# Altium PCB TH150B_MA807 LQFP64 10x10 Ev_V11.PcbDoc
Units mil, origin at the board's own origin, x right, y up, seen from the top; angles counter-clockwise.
Board outline 2850 x 2505 mil, 2 copper layers (Top Layer, Bottom Layer); 50 components, 79 nets, 342 pads, 184 vias.
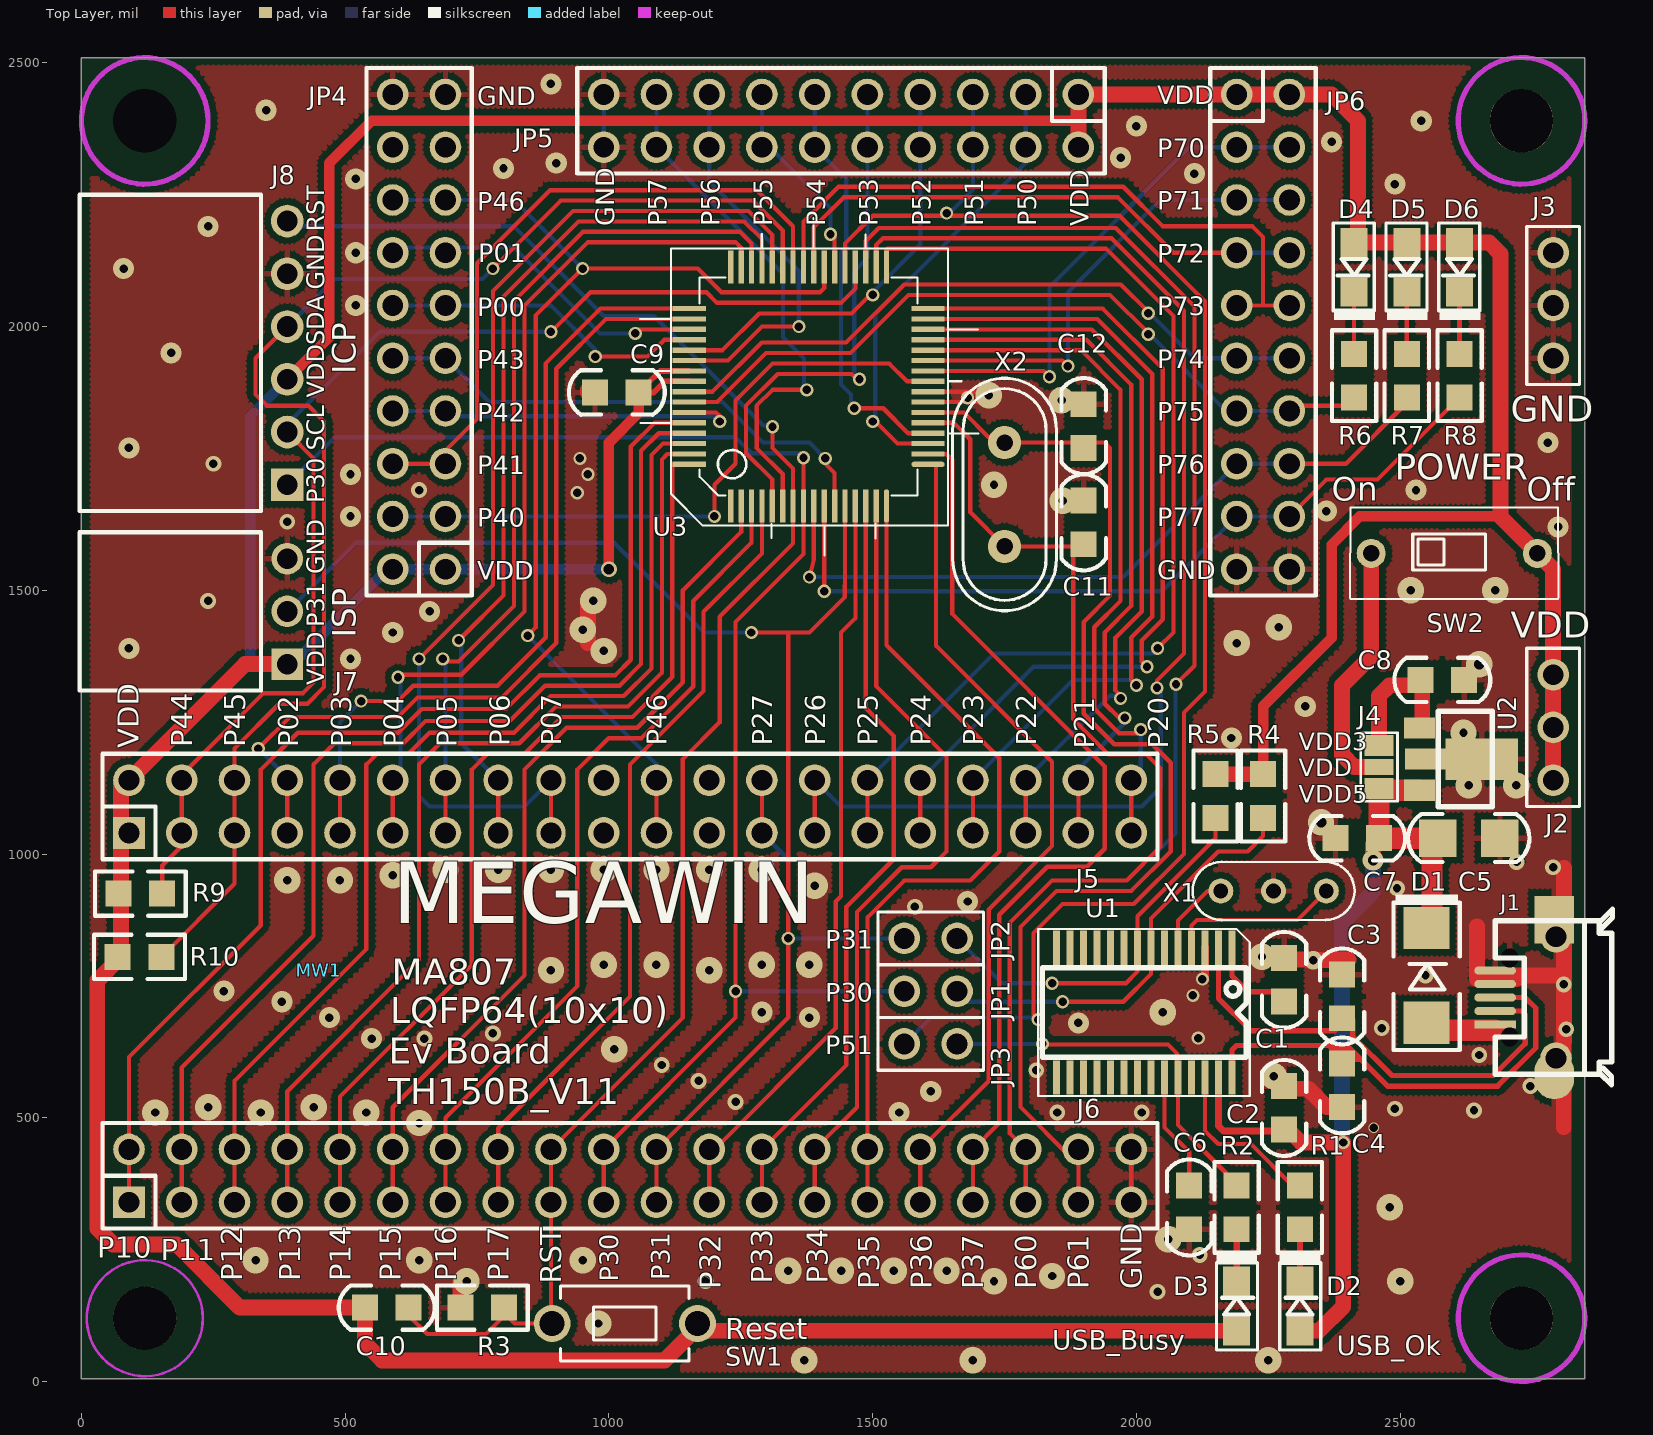
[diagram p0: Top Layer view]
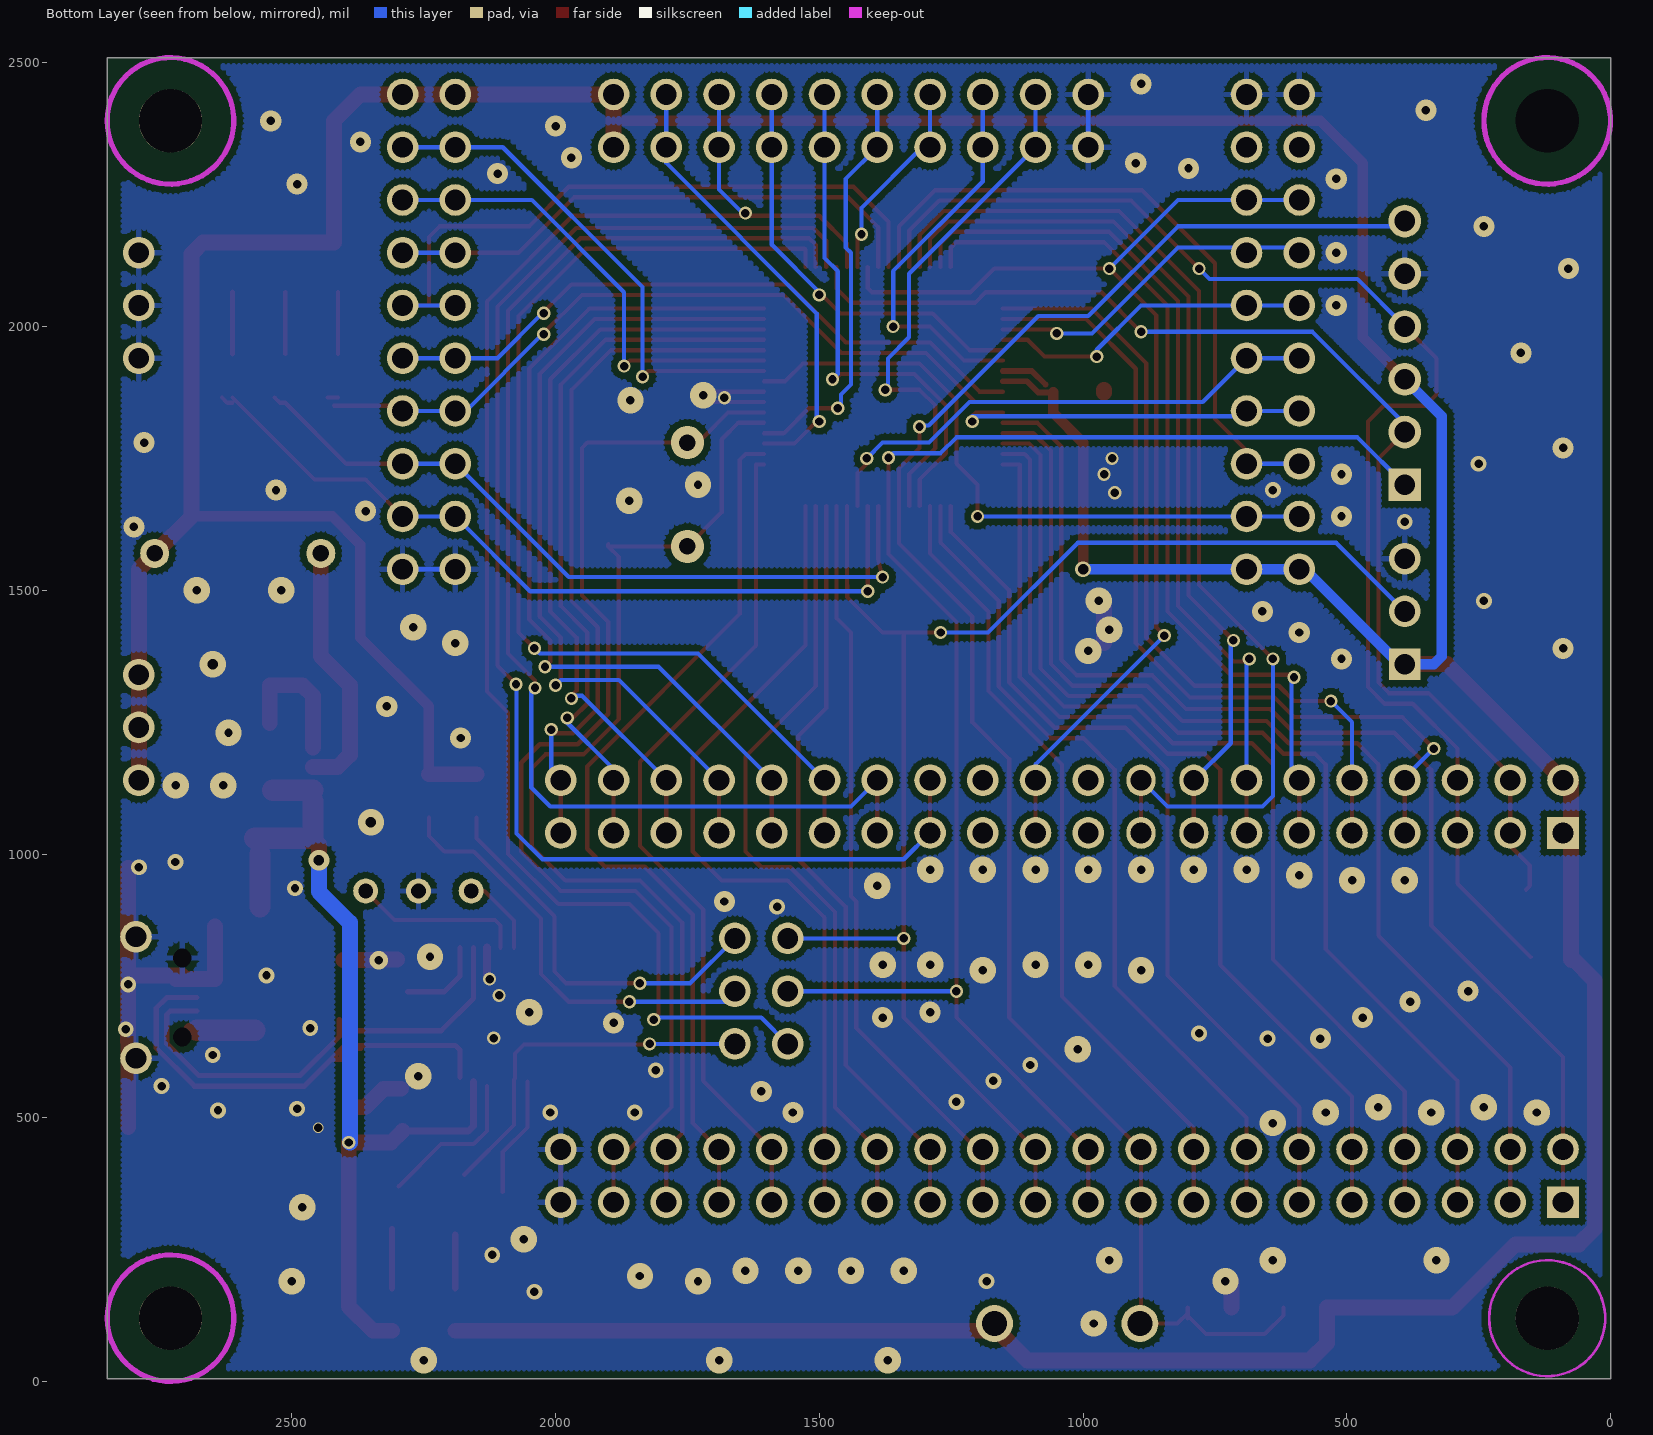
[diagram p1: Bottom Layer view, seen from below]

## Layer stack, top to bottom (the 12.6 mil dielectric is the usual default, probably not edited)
Top Layer: signal copper 1.4
Dielectric: dielectric 12.6, FR-4, Dk 4.8
Bottom Layer: signal copper 1.4

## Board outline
0,5 0,2510 2850,2510 2850,5

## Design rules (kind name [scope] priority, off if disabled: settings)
Clearance 12 [All] p1 off: gap=12
Clearance 10 [All] p2 off: gap=10
Clearance 6 [All] p3: gap=6
ComponentClearance [All] p1 off: gap=10 collisioncheckmode=3 verticalgap=10 showdistances=FALSE
HoleSize [All] p1: absolutevalues=TRUE maxlimit=500 minlimit=1 maxpercent=80.000 minpercent=20.000
MinimumSolderMaskSliver [All] p1 off: minsoldermaskwidth=10
PolygonConnect VIA [ISVIA] p1: connectstyle=Direct reliefconductorwidth=10 reliefentries=4 polygonreliefangle="90 Angle"
PolygonConnect [All] p2: connectstyle=Relief reliefconductorwidth=10 reliefentries=4 polygonreliefangle="90 Angle"
RoomDefinition "TH150B_MA807 LQFP64 Ev_V10" [InComponentClass('TH150B_MA807 LQFP64 Ev_V10')] p1: confinementstyle=ConfineIn formatcopy=TRUE lockcomponents=FALSE outline -530,-1140 3370,-1140 3370,2770 -530,2770
RoutingVias [All] p1: holewidth=16 width=25 viastyle="Through Hole" minholewidth=16 minwidth=24 maxholewidth=28 maxwidth=50
SilkToSilkClearance [All] p1 off: silktosilkclearance=10
SilkscreenOverComponentPads [All] p1 off: minsilkscreentomaskgap=10
SolderMaskExpansion [All] p1 off: expansion=4
Width [All] p1: maxlimit=200 minlimit=6 preferedwidth=10
23 further rules are at their usual default settings.

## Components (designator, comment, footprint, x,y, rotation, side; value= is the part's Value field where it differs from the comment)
C1 "4.7uF" 0805C 2280,761.34 r90 top
C2 "0.1uF" 0805C 2280,518.66 r270 top
C3 "15pF" 0805C 2390,730 r90 top
C4 "15pF" 0805C 2390,561.34 r270 top
C5 "4.7uF" 1206C 2630,1030 r0 top
C6 "0.1uF" 0805C 2100,330 r90 top
C7 "0.1uF" 0805C 2418.66,1030 r180 top
C8 "4.7uF" 0805C 2580,1330 r0 top
C9 "0.1uF" 0805C 1014.92,1875.08 r180 top
C10 "1u" 0805C 578.66,140 r0 top
C11 "NC" 0805C 1900,1628.66 r90 top
C12 "NC" 0805C 1900,1811.34 r90 top
D1 "1N5817" D5817_SMD_1 2550,770 r270 top
D2 "Yellow" 0805D 2310,143.08 r90 top
D3 "RED" 0805D 2190,143.08 r90 top
D4 "Green" 0805D 2412.54,2112.47 r270 top
D5 "Red" 0805D 2512.54,2112.47 r270 top
D6 "Green" 0805D 2612.54,2112.47 r270 top
J1 "Micro USB母座" JACK_USB_SMD290X220P065 2680,727.95 r180 top
J2 "*" PS3P254 2790,1140 r90 top
J3 "*" PS3P254 2790,2140 r270 top
J4 "*" JUMP3_SMD 2460,1165 r90 top
J5 "*" PS20X2P254#1 90,1040 r0 top locked
J6 "*" PS20X2P254#2 90,340 r0 top locked
J7 "*" PS3P254f_90 390,1360 r90 top
J8 "*" PS6P254F_90 390,1700 r90 top
JP1 "JUMPER2" PS2P254 1560,740 r0 top
JP2 "JUMPER2" PS2P254 1560,840 r0 top
JP3 "JUMPER2" PS2P254 1560,640 r0 top
JP4 "*" PS10X2P254 690,1540 r90 top
JP5 "*" PS10X2P254 1890,2440 r180 top
JP6 "*" PS10X2P254 2190,2440 r270 top
MW1 "MW-A4" MEGAWIN_T 450,780 r0 top
R1 "1K" 0805R 2310,330 r270 top
R2 "1K" 0805R 2190,330 r270 top
R3 "47K" 0805R 760,140 r0 top
R4 "4.7K" 0805R 2240,1110 r270 top
R5 "4.7K" 0805R 2150,1110 r270 top
R6 "1K" 0805R 2412.54,1906.89 r90 top
R7 "1K" 0805R 2512.54,1906.89 r90 top
R8 "1K" 0805R 2612.54,1906.89 r90 top
R9 "4.7K" 0805R 111.66,925 r180 top
R10 "4.7K" 0805R 110,805 r180 top
SW1 "SW TACT-SPST" SW_T_2P 1030,110 r180 top
SW2 "-" DIP2_SW 2445.04,1570 r0 top
U1 "MA101_TSSOP28" TSSOP28_170P065 2014.84,699.52 r180 top
U2 "AIC1734-33(SOT-89)" SOT89 2536.53,1180 r270 top
U3 "MA807_LQFP64(10x10)" QFP64_10X10P050 1230.95,1660 r90 top locked (schematic designator U1)
X1 "6MHz" X3P 2360,930 r180 top
X2 "NC" X49U 1750,1681.58 r90 top

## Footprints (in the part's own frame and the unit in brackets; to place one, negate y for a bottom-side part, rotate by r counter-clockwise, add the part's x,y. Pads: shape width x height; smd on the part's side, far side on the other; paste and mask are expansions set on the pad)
0805C [mm]
  rect 1.25x1.25 smd: 1(-1.05,0) 2(1.05,0)
  silkscreen extent -2.31,-1.07 2.31,1.07
0805D [mm]
  rect 1.4x1.3 smd: 1(-1.192,0) 2(1.192,0)
  silkscreen extent -2.12,-1 2.53,0.98
0805R [mm]
  rect 1.25x1.25 smd: 1(-1.05,0) 2(1.05,0)
  silkscreen extent -2.18,-1.07 2.18,1.07
1206C [mm]
  rect 1.8x1.8 smd: 1(-1.5,0) 2(1.5,0)
  silkscreen extent -2.92,-1.15 2.92,1.16
D5817_SMD_1 [mil]
  rect 80x86.61 smd: 1(90,0) 2(-90,0)
  silkscreen extent -153,-63 142,63
DIP2_SW [mm]
  round 1.4 hole 0.8: 1(0,0) 2(8,0)
  silkscreen extent -1.02,-2.2 9.02,2.2
JACK_USB_SMD290X220P065 [mm]
  rect 1.9x1.8 on Mech2: 0(-2.85,-1.15) 0(-2.85,1.15)
  round 0.8 hole 0.9 unplated: 1(-0.7,1.9) 5(-0.7,-1.9)
  rect 2x0.4 smd: 1(0,1.3)
  oval 2x0.4 smd: 2(0,0.65) 3(0,0) 4(0,-0.65) 5(0,-1.3)
  round 1.524 hole 1: 5(-2.931,2.921) 5(-2.931,-2.921)
  oval 1.9x2.3 smd: 5(-2.85,3.75)
  rect 1.9x2.3 smd: 5(-2.85,-3.75)
  silkscreen extent -5.65,-4.25 -0.01,4.2
JUMP3_SMD [mil]
  rect 40x55 smd: 1(-41,0) 3(41,0)
  rect 30x55 smd: 2(0,0)
  silkscreen extent -65,-35 65,35
MEGAWIN_T [mil]
PS2P254 [mil]
  round 60 hole 39.37: 1(0,0) 2(100,0)
  silkscreen extent -50,-50 150,50
PS3P254 [mil]
  round 60 hole 39.37: 1(0,0) 2(100,0) 3(200,0)
  silkscreen extent -50,-50 250,50
PS3P254f_90 [mil]
  rect 60x60 hole 39.37: 1(0,0)
  round 60 hole 39.37: 2(100,0) 3(200,0)
  silkscreen extent -50,50 250,394
PS6P254F_90 [mil]
  rect 62x62 hole 39.37: 1(0,0)
  round 62 hole 39.37: 2(100,0) 3(200,0) 4(300,0) 5(400,0) 6(500,0)
  silkscreen extent -50,50 550,394
PS10X2P254 [mil]
  round 60 hole 39.37: 1(0,0) 2(0,100) 3(100,0) 4(100,100) 5(200,0) 6(200,100) 7(300,0) 8(300,100) 9(400,0) 10(400,100) 11(500,0) 12(500,100) 13(600,0) 14(600,100) 15(700,0) 16(700,100) 17(800,0) 18(800,100) 19(900,0) 20(900,100)
  silkscreen extent -50,-50 950,150
PS20X2P254#1 [mil]
  rect 60x60 hole 39.37: 1(0,0)
  round 60 hole 39.37: 2(0,100) 3(100,0) 4(100,100) 5(200,0) 6(200,100) 7(300,0) 8(300,100) 9(400,0) 10(400,100) 11(500,0) 12(500,100) 13(600,0) 14(600,100) 19(900,0) 20(900,100) 21(1000,0) 22(1000,100) 23(1100,0) 24(1100,100) 25(1200,0) 26(1200,100) 27(1300,0) 28(1300,100) 29(1400,0) 30(1400,100) 31(1500,0) 32(1500,100) 33(1600,0) 34(1600,100) 35(1700,0) 36(1700,100) 37(1800,0) 38(1800,100) 39(1900,0) 40(1900,100)
  oval 55x60 hole 39.37: 15(700,0) 16(700,100) 17(800,0) 18(800,100)
  silkscreen extent -50,-50 1950,150
PS20X2P254#2 [mil]
  rect 60x60 hole 39.37: 1(0,0)
  round 60 hole 39.37: 2(0,100) 3(100,0) 4(100,100) 5(200,0) 6(200,100) 7(300,0) 8(300,100) 9(400,0) 10(400,100) 11(500,0) 12(500,100) 13(600,0) 14(600,100) 15(700,0) 16(700,100) 17(800,0) 18(800,100) 19(900,0) 20(900,100) 21(1000,0) 22(1000,100) 23(1100,0) 24(1100,100) 25(1200,0) 26(1200,100) 27(1300,0) 28(1300,100) 29(1400,0) 30(1400,100) 31(1500,0) 32(1500,100) 33(1600,0) 34(1600,100) 35(1700,0) 36(1700,100) 37(1800,0) 38(1800,100) 39(1900,0) 40(1900,100)
  silkscreen extent -50,-50 1950,150
QFP64_10X10P050 [mm]
  rect 1.6x0.254 smd: 1(0,0) 2(0,-0.5) 3(0,-1) 4(0,-1.5) 5(0,-2) 6(0,-2.5) 7(0,-3) 8(0,-3.5) 9(0,-4) 10(0,-4.5) 11(0,-5) 12(0,-5.5) 13(0,-6) 14(0,-6.5) 15(0,-7) 33(11.5,-7.5) 34(11.5,-7) 35(11.5,-6.5) 36(11.5,-6) 37(11.5,-5.5) 38(11.5,-5) 39(11.5,-4.5) 40(11.5,-4) 41(11.5,-3.5) 42(11.5,-3) 43(11.5,-2.5) 44(11.5,-2) 45(11.5,-1.5) 46(11.5,-1) 47(11.5,-0.5) 48(11.5,0)
  oval 1.6x0.254 smd: 16(0,-7.5)
  oval 0.254x1.6 smd: 17(2,-9.5)
  rect 0.254x1.6 smd: 18(2.5,-9.5) 19(3,-9.5) 20(3.5,-9.5) 21(4,-9.5) 22(4.5,-9.5) 23(5,-9.5) 24(5.5,-9.5) 25(6,-9.5) 26(6.5,-9.5) 27(7,-9.5) 28(7.5,-9.5) 29(8,-9.5) 30(8.5,-9.5) 31(9,-9.5) 32(9.5,-9.5) 49(9.5,2) 50(9,2) 51(8.5,2) 52(8,2) 53(7.5,2) 54(7,2) 55(6.5,2) 56(6,2) 57(5.5,2) 58(5,2) 59(4.5,2) 60(4,2) 61(3.5,2) 62(3,2) 63(2.5,2) 64(2,2)
  silkscreen extent -2.4,-11.92 13.86,4.36
SOT89 [mm]
  rect 1.016x1.5 smd: 1(-1.5,0) 3(1.5,0)
  rect 2x3.5 smd: 2(0,3)
  rect 1.016x2.6 smd: 2(0,0.6)
  silkscreen extent -2.3,0.9 2.3,3.5
SW_T_2P [mil]
  round 70 hole 47.24: 1(-137.79,0) 2(137.79,0)
  silkscreen extent -122,-71 122,71
TSSOP28_170P065 [mil]
  rect 13x65 smd: 1(-166.34,-123) 2(-140.75,-123) 3(-115.16,-123) 4(-89.57,-123) 5(-63.98,-123) 6(-38.39,-123) 7(-12.79,-123) 8(12.8,-123) 9(38.39,-123) 10(63.98,-123) 11(89.57,-123) 12(115.16,-123) 13(140.75,-123) 14(166.34,-123) 15(166.34,123) 16(140.75,123) 17(115.16,123) 18(89.57,123) 19(63.98,123) 20(38.39,123) 21(12.8,123) 22(-12.79,123) 23(-38.39,123) 24(-63.98,123) 25(-89.57,123) 26(-115.16,123) 27(-140.75,123) 28(-166.34,123)
  silkscreen extent -200,-158 201,158
X3P [mm]
  round 1.2 hole 0.711: 1(0,0) 2(5.08,0) 3(2.54,0)
  silkscreen extent -1.36,-1.4 6.44,1.4
X49U [mm]
  round 1.6 hole 0.8: 1(-2.5,0) 2(2.5,0)
  silkscreen extent -5.6,-2.5 5.6,2.5

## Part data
C1 C5 C8: library part CAP
C2 C3 C4 C6 C7 C9: library part "CAP NP"
C10: library part C
C11 C12: library part "C NP"
D1: library part DIODE_ZD, "Schottky Diode"
D2 D3 D4 D5 D6: library part LED
J1: library part CON5, "Connector"
J2 J3 J4 J7: library part CON3
J5 J6: library part CON40A
J8: library part CON6
JP4 JP5 JP6: library part CON10X2
R1 R2 R4 R5 R6 R7 R8: library part R_Dup1
R3 R9 R10: library part R
SW2: library part SW-2
U2: library part AIC1734-33(SOT-89)_0
U3: library part MG82Fx3xx_0
X1: library part CRYSTAL_RC
X2: library part CRYSTAL

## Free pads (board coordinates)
  round 120 hole 120 unplated: 0(120,120) 0(2730,120) 0(2730,2390)
  round 40 hole 120 unplated: 0(120,2390)

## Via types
v1: diameter 50, hole 16, Top Layer to Bottom Layer, tented both sides, 58 vias
v2: diameter 25, hole 16, Top Layer to Bottom Layer, tented both sides, 54 vias
v3: diameter 40, hole 16, Top Layer to Bottom Layer, tented both sides, 39 vias
v4: diameter 30, hole 16, Top Layer to Bottom Layer, tented both sides, 27 vias
v5: diameter 50, hole 20, Top Layer to Bottom Layer, tented both sides, 2 vias
v6: diameter 30, hole 20, Top Layer to Bottom Layer, tented both sides, 1 vias
v7: diameter 39.37, hole 20, Top Layer to Bottom Layer, tented both sides, 1 vias
v8: diameter 20, hole 16, Top Layer to Bottom Layer, tented both sides, 1 vias
v9: diameter 35, hole 16, Top Layer to Bottom Layer, tented both sides, 1 vias

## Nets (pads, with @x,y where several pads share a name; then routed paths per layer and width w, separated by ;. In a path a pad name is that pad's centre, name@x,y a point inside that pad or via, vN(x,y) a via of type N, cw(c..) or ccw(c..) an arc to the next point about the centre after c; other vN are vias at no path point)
D+: C4.1 J1.3 U1.28 | length 938.6
  Top Layer w10: U1.28 2181.18,628.18 2190,637 2386.34,637 ; 2368.82,631.18 2390,631.18 2392.16,631.18 ; C4.1@2390,611.18 2424.48,611.18 ; C4.1@2405.33,618.01 2392.16,631.18 ; J1.3 2736.93,727.95 2757,707.88 2757,632.23 2684.77,560 2476,560 2411.66,624.34 2399,637 2386.34,637 ; 2386.34,637 2392.16,631.18
D-: C3.1 J1.2 U1.2 | length 907.4
  Top Layer w10: U1.2 2155.59,726.25 2216.84,665 2376,665 2390,679 C3.1@2406,679 ; C3.1@2410,686 2410,654.28 2484.28,580 2676.49,580 2737,640.51 2737,695.8 2730.43,702.36 J1.2
GND_POWER: C1.2 C2.1 C3.2 C4.2 C5.2 C6.1 C7.2 C8.2 C9.2 C11.2 C12.2 J1.4 J1.5 J3.1 J3.2 J3.3 J6.39 J6.40 J7.3 J8.5 JP4.19 JP4.20 JP5.19 JP5.20 JP6.19 JP6.20 R3.1 U1.3 U2.2 U3.23 U3.24 X1.3 | length 1666.9
  Top Layer w8: U3.23 1680,1856.85 v1@1705.98,1856.85 ; U3.24 1680,1876.53 v1@1705.98,1876.53 ; J6.39 J6.40
  Top Layer w15: v2@2130,763 U1.3
  Top Layer w30: R3.1 v1@718.66,190 ; 960,1400 960,1425 v1@960,1480 ; C9.2@960,1875.08 C9.2@960,1880 ; C2.1@2293,555 2326,555 2361,520 C4.2 ; C1.2@2300,800 v9@2327.66,800 ; v9@2330,799 v9(2335,799) 2390,799 2402,799 ; 2645.87,763 2680,763 2719.29,763 ; 2645.87,765.59 2645.87,779.13 2645.87,862.68 ; 2708.54,770 2805.63,770 ; 2810,482 2810.17,580.28 2810.23,612.93 2810.33,667.96 2810.48,752.95 2810.64,842.93 2810.69,875.56 2810.87,973.68
  Bottom Layer w8: JP5.20 JP5.19 ; JP6.19 JP6.20
  other v1: 1370,40 1690,40 2250,40 980,110 730,190 1730,190 2500,190 1840,200 1340,210 1440,210 1540,210 1640,210 330,230 640,230 950,230 2060,270 2480,330 640,490 140,510 340,510 540,510 240,520 440,520 2260,579 1010,630 2050,700 890,780 1190,780 990,790 1090,790 1290,790 1380,790 2238,805 1390,940 390,950 490,950 590,960 690,970 790,970 890,970 990,970 1090,970 1190,970 1290,970 2630,1130 2720,1130 2620,1230 990,1385 2190,1400 950,1425 2270,1430 970,1480 2520,1500 2680,1500 1860,1670 1730,1700 1858,1860 1720,1870
  other v2: 2117,651 2107,732 2125,763 940,1685 960,1720 945,1750 1680,1865
  other v3: 1550,510 1610,550 550,650 1890,680 470,690 1380,690 1290,700 380,720 270,740 1680,910 2180,1220 2320,1280 510,1370 90,1390 590,1420 660,1460 2799.51,1620.07 510,1640 2360,1650 2530,1690 510,1720 90,1770 2780,1780 170,1950 520,2040 80,2110 520,2140 240,2190 2490,2270 520,2280 2110,2290 800,2300 900,2310 1970,2320 2370,2350 2000,2380 2540,2390 350,2410 890,2460
  other v4: 2040,170 1182.79,190 2120,240 1850,510 2010,510 2640,514 2490,517 1240,530 2747,560 1170,570 1810,590 1100,600 2650,619 650,650 780,660 2815,667.95 2465,670 2810,752.95 2548,770 1580,900 2494,935 2790,975 2720.73,984.9 240,1480 390,1630 640,1690 250,1740
  other v5: 2350,1060 2650,1360
  other v8: 2450,481
MA101_RX: JP2.2 R5.2 U1.8 | length 739.3
  Top Layer w8: v2(1840,755) 1980,755 2002.05,777.05 U1.8 2002.05,882.05 2150,1030 R5.2
  Bottom Layer w8: JP2.2 1745,755 v2(1840,755)
MA101_TX: JP1.2 R4.2 U1.7 | length 806.2
  Top Layer w8: v2(1860,720) 1975,720 2027.64,772.64 U1.7 2027.64,877.64 2155,1005 2211,1005 2240,1034 R4.2
  Bottom Layer w8: JP1.2@1660,720 v2(1860,720)
NetC1_1: C1.1 U1.1 | length 165
  Top Layer w10: U1.1 2181.18,768.82 2211.34,738.66 C1.1@2280,738.66
NetC6_2: C6.2 U1.23 | length 229.4
  Top Layer w8: U1.23@2053.23,569 2053.23,481.77 2100,435 C6.2 C6.2@2100,359
NetD1_1: D1.1 J1.1 | length 120.9
  Top Layer w30: 2680,665.87 2690.87,665.87
  Top Layer w40: D1.1@2570,665.87 2680,665.87
NetD2_2: D2.2 R1.2 | length 111.7
  Top Layer w12: D2.2@2310,176.92 D2.2 R1.2
NetD3_2: D3.2 R2.2 | length 101.7
  Top Layer w12: D3.2@2190,176.92 D3.2 R2.2@2190,278.66
NetD4_2: D4.2 R6.2 | length 117.3
  Top Layer w8: R6.2 D4.2
NetD5_2: D5.2 R7.2 | length 117.3
  Top Layer w8: R7.2 D5.2
NetD6_2: D6.2 R8.2 | length 117.3
  Top Layer w10: R8.2 D6.2
NetJ4_2: J4.2 SW2.1 | length 484.3
  Top Layer w30: SW2.1 2445.04,1375.04 2390,1320 2390,1187.99 2412.99,1165 J4.2
NetU1_4: U1.4 X1.1 | length 324.6
  Top Layer w8: U1.4 2104.41,864.41 2115,875 2305,875 X1.1
NetU1_5: U1.5 X1.2 | length 155.8
  Top Layer w8: U1.5 2078.82,873.82 2135,930 X1.2
P00: JP4.11 JP4.12 U3.52 | length 620.2
  Top Layer w8: v2(974,1943) 1073,1943 1104.96,1974.96 U3.52
  Bottom Layer w8: JP4.12 JP4.11 890,2040 974,1956 v2@974,1946
P01: JP4.13 JP4.14 U3.51 | length 619.7
  Top Layer w8: v2@1050,1994.65 U3.51
  Bottom Layer w8: JP4.14@600,2150 690,2150 820,2150 983,1987 v2(1050,1987)
P02: J5.7 J5.8 U3.50 | length 1641.9
  Top Layer w8: v2(335,1200) 395,1260 600,1260 637,1297 797,1297 900,1400 900,1920 994.33,2014.33 U3.50 ; J5.7 J5.8
  Bottom Layer w8: v2(335,1200) 390,1145 J5.8
P03: J5.9 J5.10 U3.49 | length 1501.6
  Top Layer w8: J5.9 J5.10 ; v2(530,1290) 600,1290 629,1319 789,1319 880,1410 880,1930 984.02,2034.02 U3.49
  Bottom Layer w8: J5.10 490,1250 v2(530,1290)
P04: J5.11 J5.12 U3.47 | length 1653.1
  Top Layer w8: J5.11 J5.12 ; v2(600,1335) 605,1340 720,1340 840,1460 840,2040 960,2160 1240,2160 1250.63,2149.37 U3.47
  Bottom Layer w8: J5.12@605,1155 v2@605,1335
P05: J5.13 J5.14 U3.46 | length 1647.8
  Top Layer w8: v2(685,1370) 690,1365 715,1365 820,1470 820,2048.67 951.01,2179.68 1248.15,2179.68 1270.31,2157.52 U3.46 ; J5.13 J5.14
  Bottom Layer w8: J5.14 v2@690,1370
P06: J5.15 J5.16 U3.45 | length 1694.9
  Top Layer w8: v2@720,1400 720,1405 720,1410 800,1490 800,2056.93 942.44,2199.37 1256.31,2199.37 1290,2165.68 U3.45 ; J5.15 J5.16
  Bottom Layer w8: v2@720,1400 720,1210 J5.16
  other v2: 715,1405
P07: J5.17 J5.18 U3.44 | length 2066.7
  Top Layer w8: v2(640,1370) 780,1510 780,2067.49 931.56,2219.05 1264.46,2219.05 1309.68,2173.83 U3.44 ; J5.17 J5.18
  Bottom Layer w8: v2(640,1370) 640,1110 660,1090 840,1090 J5.18
P10: J6.1 J6.2 U3.60 | length 2264
  Top Layer w8: J6.1 J6.2 90,615 340,865 340,1111 ; 340,1130 340,1111 ; U3.60 1086.13,1817.48 1041.26,1772.62 1041.26,1368.26 1011.74,1338.74 868.74,1338.74 805,1275 645,1275 600,1230 410,1230 340,1160 340,1111
P11: J6.3 J6.4 U3.61 | length 2142.7
  Top Layer w8: J6.3 J6.4 190,595 440,845 440,1170 480,1210 610,1210 652,1252 812,1252 879.06,1319.06 1019.89,1319.06 1060.94,1360.11 1060.94,1764.46 1094.28,1797.8 U3.61
P12: J6.5 J6.6 U3.62 | length 2059.5
  Top Layer w8: J6.5 J6.6 290,570 540,820 540,1140 ; 540,1165 540,1140 ; U3.62 1102.43,1778.11 1080.63,1756.31 1080.63,1351.95 1028.05,1299.37 889.37,1299.37 820,1230 660,1230 620,1190 560,1190 540,1170 540,1140
P13: J6.7 J6.8 U3.63 | length 1941.4
  Top Layer w8: J6.7 J6.8 390,550 640,800 640,1150 ; 640,1165 640,1150 ; U3.63 1110.59,1758.43 1100.32,1748.15 1100.32,1343.8 1036.2,1279.69 899.68,1279.69 830,1210 680,1210 640,1170 640,1150
P14: J6.9 J6.10 U3.64 | length 1811.6
  Top Layer w8: J6.9 J6.10 490,540 740,790 740,1160 770,1190 840,1190 910,1260 1044.36,1260 1120,1335.65 1120,1738.74 U3.64
P15: J6.11 J6.12 U3.2 | length 1672.3
  Top Layer w8: J6.11 J6.12 590,520 840,770 840,1160 919.37,1239.37 1053.72,1239.37 1140,1325.65 1140,1500 1250.63,1610.63 U3.2
P16: J6.13 J6.14 U3.3 | length 1596.8
  Top Layer w8: J6.13 J6.14 690,500 940,750 940,1160 999.69,1219.69 1061.88,1219.69 1159.68,1317.49 1159.68,1479.68 1270.31,1590.31 U3.3
P17: J6.15 J6.16 U3.4 | length 1527.1
  Top Layer w8: J6.15 J6.16 790,480 1040,730 1040,1169.97 1179.37,1309.34 1179.37,1459.37 1290,1570 U3.4
P20: J5.39 J5.40 U3.28 | length 1354.8
  Top Layer w8: U3.28 1894.72,1955.28 1970,1880 1970,1480 1920,1430 1920,1276 1967,1229 2001,1229 v2(2008,1236) ; J5.39 J5.40
  Bottom Layer w8: J5.40 1990,1130 1995,1135 2008,1148 v2(2008,1236)
P21: J5.37 J5.38 U3.29 | length 1334.3
  Top Layer w8: U3.29 1905.04,1974.96 1990,1890 1990,1470 1940,1420 1940,1285 1966.5,1258.5 1978,1258.5 1978.5,1258.5 v2@1983,1254 ; J5.37 J5.38@1890,1120
  Bottom Layer w8: J5.38 1890,1161 1982.5,1253.5 v2@1983,1254
  other v2: 1978,1258
P22: J5.35 J5.36 U3.30 | length 1405.4
  Top Layer w8: U3.30 1915.35,1994.65 2010,1900 2010,1460 1960,1410 1960,1310 v2@1970,1300 ; J5.35 J5.36@1790,1130
  Bottom Layer w8: J5.36 1950,1300 v2@1970,1300
  other v2: 1970,1295
P23: J5.33 J5.34 U3.31 | length 1571.8
  Top Layer w8: U3.31 1925.67,2014.33 2030,1910 2030,1450 1990,1410 1990,1330 v2(2000,1320) ; J5.33 J5.34
  Bottom Layer w8: J5.34 1880,1330 1990,1330 v2(2000,1320)
P24: J5.31 J5.32 U3.32 | length 1697
  Top Layer w8: J5.31 J5.32 ; U3.32 1935.98,2034.02 2050,1920 2050,1445 2010,1405 2010,1365 v2(2020,1355)
  Bottom Layer w8: J5.32 1805,1355 v2(2020,1355)
P25: J5.29 J5.30 U3.33 | length 2106.7
  Top Layer w8: J5.30@1490,1120 J5.29 J5.30 ; U3.33 1526.22,2146.22 1527.7,2147.7 1942.3,2147.7 2070,2020 2070,1420 v2(2040,1390)
  Bottom Layer w8: J5.30 1730,1380 2030,1380 v2(2040,1390)
P26: J5.27 J5.28 U3.34 | length 2397
  Top Layer w8: J5.27 J5.28@1390,1130 ; U3.34 1506.53,2154.37 1519.54,2167.38 1952.62,2167.38 2090,2030 2090,1380 2039,1329 v2(2039,1315)
  Bottom Layer w8: J5.28 1440,1090 2010,1090 2046,1126 2046,1308 v2(2039,1315)
P27: J5.25 J5.26 U3.35 | length 2683.2
  Top Layer w8: J5.25 J5.26 ; U3.35 1486.85,2162.53 1511.39,2187.07 1960.77,2187.07 2110,2037.84 2110,1357 v2(2075,1322)
  Bottom Layer w8: J5.25 1340,990 2025,990 2074,1039 v2@2074,1322
P30_RXD: J6.19 J6.20 J8.1 JP1.1 U3.8 | length 2945.7
  Top Layer w8: J6.19 J6.20 1240,690 v2(1240,740) 1240,1440 1368.74,1568.74 U3.8 v2(1368.74,1751.26)
  Bottom Layer w8: J8.1 480,1790 1240,1790 1270,1760 1360,1760 v2(1368.74,1751.26) ; J6.20@972,458 J6.20 ; v2(1240,740) JP1.1
P31_TXD: J6.21 J6.22 J7.2 JP2.1 U3.12 | length 2785.6
  Top Layer w8: J6.21 J6.22 1340,690 v2(1340,840) 1340,1420 ; v2(1270,1420) 1340,1420 ; 1447.16,1509.68 1447.16,1487.16 1380,1420 1340,1420 ; 1447.48,1509.68 U3.12
  Bottom Layer w8: J7.2 520,1590 1010,1590 1180,1420 v2(1270,1420) ; v2(1340,840) JP2.1
P32: J6.23 J6.24 U3.13 | length 1440.7
  Top Layer w8: J6.23 J6.24 1200,440 1430,670 1430,910 1440,920 1440,1420 1467.16,1447.16 U3.13
P33: J6.25 J6.26 U3.14 | length 1445.6
  Top Layer w8: J6.25 J6.26 1450,600 1450,900 1540,990 1540,1223.85 1486.85,1277 U3.14
P34: J6.27 J6.28 U3.15 | length 1511.1
  Top Layer w8: J6.27 J6.28 1470,520 1470,890 1555,975 1610,975 1640,1005 1640,1185 1506.53,1318.47 U3.15
P35: J6.29 J6.30 U3.16 | length 1585.3
  Top Layer w8: J6.29 J6.30 1490,880 1560,950 1685,950 1740,1005 1740,1182 1526.22,1395.78 U3.16
P36: J6.31 J6.32 U3.17 | length 1608.5
  Top Layer w8: J6.31 J6.32 1720,570 1720,895 1840,1015 1840,1175 1620,1395 1620,1738.74 U3.17
P37: J6.33 J6.34 U3.18 | length 1724.9
  Top Layer w8: U3.18 1639.41,1758.42 1650.95,1746.89 1650.95,1455.05 1940,1166 1940,1010 1905.99,975.99 1830.99,975.99 1740,885 1740,490 J6.34 J6.33
P40: JP4.3 JP4.4 U3.25 | length 1254.5
  Top Layer w8: v2(1200,1640) 1200,1700 1240,1740 1240,1860 1310,1930 1531.22,1930 1565,1896.22 U3.25
  Bottom Layer w8: JP4.4 JP4.3 v2(1200,1640)
P41: JP4.5 JP4.6 U3.42 | length 1352.3
  Top Layer w8: JP4.6 665,1740 677.5,1752.5 750,1825 750,2120 888.42,2258.42 1280.77,2258.42 1349.05,2190.14 U3.42
  Bottom Layer w8: JP4.6 JP4.5
P42: JP4.7 JP4.8 U3.59 | length 670.8
  Top Layer w8: U3.59 1202.83,1837.17 v2@1210,1830
  Bottom Layer w8: JP4.8 JP4.7 ; JP4.7@700,1830 v2@1210,1830
  other v2: 1210,1820
P43: JP4.9 JP4.10 U3.11 | length 993.1
  Top Layer w8: v2@1405,1745 1427.79,1722.21 U3.11
  Bottom Layer w8: JP4.10 JP4.9 773.15,1856.85 1215,1856.85 1291.85,1780 1380,1780 v2(1410,1750)
P44: J5.3 J5.4 J8.2 R9.1 U3.36 | length 2295.4
  Top Layer w8: R9.1@160.33,932.33 153,939.66 153,978 J5.3@190,1015 ; J5.3 J5.4 190,1150 345,1305 420,1305 440,1325 440,1750 J8.2 ; v2(890,1990) 965,2065 1185,2065 1205,2045 1440,2045 1467.16,2072.16 U3.36
  Bottom Layer w8: J8.2@400,1790 J8.2 382.5,1807.5 565,1990 v2@880,1990
P45: J5.5 J5.6 J8.4 R10.1 U3.43 | length 2624
  Top Layer w8: R10.1 290,943.66 J5.5 J5.6 290,1200 375,1285 428.28,1285 460,1316.72 460,1820 430,1850 351.34,1850 330,1871.34 330,1940 J8.4 ; v2(780,2110) 908.74,2238.74 1272.62,2238.74 1329.37,2181.99 U3.43
  Bottom Layer w8: J8.4@400,1990 J8.4 480,2090 760,2090 v2(780,2110)
P46: J5.21 J5.22 JP4.15 JP4.16 U3.39 | length 2147.9
  Top Layer w8: v2(845.87,1414.13) 861,1429.27 861,2021 v2(950,2110) 1168.28,2110 1213.28,2065 1400,2065 1408.11,2073.11 U3.39 ; J5.21 J5.22
  Bottom Layer w8: JP4.16 JP4.15 820,2240 v2(950,2110) ; v2(845.87,1414.13) 1090,1170 J5.22
P50: JP5.3 JP5.4 U3.19 | length 860.4
  Top Layer w8: v2(1500,1820) 1505,1820 1546.89,1778.11 U3.19
  Bottom Layer w8: v2@1505,1820 1505,2025 1790,2310 JP5.4 JP5.3
P51: JP3.1 JP5.5 JP5.6 U3.37 | length 2921.8
  Top Layer w8: U3.37 1447.48,2157.48 1500,2210 1640,2210 1967.84,2210 2130,2047.84 2130,1308 2090,1268 2090,1000 1995,905 1860,905 1805,850 1805,690 v2@1813.84,690
  Bottom Layer w8: JP3.1 1610,690 v2@1813.84,690 ; v2@1640,2210 1642.5,2212.5 1690,2260 JP5.6 JP5.5
  other v2: 1813.84,686 1640,2215
P52: JP5.7 JP5.8 U3.53 | length 805.5
  Top Layer w8: U3.53 1215.28,1955.28 1285,2025 1460,2025 v2@1497.5,2062.5
  Bottom Layer w8: v2@1497.5,2062.5 1590,2155 JP5.8 JP5.7
  other v2: 1500,2060
P53: JP5.9 JP5.10 U3.5 | length 1011.1
  Top Layer w8: U3.5 1309.68,1710 1260,1759.69 1260,1850 1320,1910 1460,1910 1472.5,1897.5 v2@1475,1895
  Bottom Layer w8: v2(1475,1900) 1465,1910 1465,2105 1490,2130 JP5.10 JP5.9
P54: JP5.11 JP5.12 U3.20 | length 791.3
  Top Layer w8: v2(1465,1845) 1520,1845 1567.21,1797.79 U3.20
  Bottom Layer w8: JP5.11 JP5.12 1450,2280 1450,2150 1440,2140 1440,1890 1458.75,1871.25 v2@1458.75,1845
P55: JP5.13 JP5.14 U3.38 | length 389.9
  Top Layer w8: U3.38 v2@1427.79,2175
  Bottom Layer w8: JP5.13 JP5.14 1305,2340 1420,2225 v2(1420,2175)
P56: JP5.15 JP5.16 U3.54 | length 744.9
  Top Layer w8: U3.54 1225.59,1935.59 1290,2000 v2(1360,2000)
  Bottom Layer w8: JP5.15 JP5.16 1190,2275 1360,2105 v2(1360,2000)
P57: JP5.17 JP5.18 U3.6 | length 998.9
  Top Layer w8: U3.6 1329.37,1720.63 1280,1770 1280,1850 1310,1880 v2(1375,1880)
  Bottom Layer w8: JP5.17 JP5.18 1330,2100 1330,1979.69 1370,1939.69 1370,1880 v2(1375,1880)
P60_X2: C11.1 J6.35 J6.36 U3.21 X2.1 | length 2052.6
  Top Layer w8: U3.21 1653.78,1817.48 1685,1786.26 1685,1648.15 X2.1 C11.1@1900,1583.15 ; J6.35 J6.36 1760,470 1760,870 1840,950 1981.72,950 2045,1013.28 2045,1163 2019,1189 1947,1189 1880,1256 1880,1563.15 C11.1@1900,1583.15 ; C11.1 C11.1@1900,1583.15
P61_X1: C12.1 J6.37 J6.38 U3.22 X2.2 | length 2230.4
  Top Layer w8: U3.22 1672.84,1837.16 1720,1790 1750,1790 1760,1790 X2.2@1770,1780 ; X2.2 X2.2@1770,1780 ; J6.37 J6.38@1890,410.3 ; J6.38 J6.38@1890,410.3 ; X2.2@1770,1780 1900,1780 1940,1780 1950,1770 1950,1490 1900,1440 1900,1266 1958,1208 2030,1208 2065,1173 2065,1005 1990,930 1848.28,930 1780,861.72 1780,520.3 1875.15,425.15 J6.38@1890,410.3
P70: JP6.3 JP6.4 U3.26 | length 969.3
  Top Layer w8: U3.26 1824.09,1915.91 v2(1835,1905)
  Bottom Layer w8: v2(1835,1905) 1835,2075 2100,2340 JP6.3 JP6.4
P71: JP6.5 JP6.6 U3.27 | length 901.9
  Top Layer w8: U3.27 1859.41,1935.59 v2(1870,1925)
  Bottom Layer w8: v2(1870,1925) 1870,2065 2045,2240 JP6.5 JP6.6
P72: JP6.7 JP6.8 U3.40 | length 1044.2
  Top Layer w8: U3.40 1388.42,2188.42 1445,2245 1965,2245 2070,2140 JP6.7
  Bottom Layer w8: JP6.7 JP6.8
P73: JP6.9 JP6.10 U3.41 | length 1349
  Top Layer w8: U3.41 1368.74,2198.74 1435,2265 1975,2265 2050,2190 2220,2190 2240,2170 2240,2045 ; JP6.9 JP6.10
  Bottom Layer w8: JP6.9 JP6.10
P74: JP6.11 JP6.12 U3.57 | length 1279.8
  Top Layer w8: U3.57 1196.54,1876.54 1289.68,1969.69 1449.68,1969.69 1559.68,2079.69 1970.32,2079.69 v2@2023.51,2026.49
  Bottom Layer w8: v2@2023.51,2026.49 2110,1940 JP6.11 JP6.12
  other v2: 2022.39,2025.36
P75: JP6.13 JP6.14 R6.1 U3.58 | length 1455.6
  Top Layer w8: U3.58 1204.69,1856.85 1297.84,1950 1457.84,1950 1567.84,2060 1950,2060 v2@2023.51,1986.49 ; JP6.14@2297.46,1850 2412.54,1850 R6.1@2420,1850 ; R6.1 R6.1@2432.54,1865.55
  Bottom Layer w8: v2@2023.51,1986.49 2170,1840 JP6.13 JP6.14
  other v2: 2022.39,1985.36
P76: JP6.15 JP6.16 R7.1 U3.9 | length 1494.7
  Top Layer w8: v2(1380,1525) 1388.43,1558.42 U3.9 1388.42,1595 ; JP6.16 2396.99,1740 2512.54,1855.55 2522.54,1855.55 R7.1@2532.54,1865.55
  Bottom Layer w8: v2(1380,1525) 1975,1525 JP6.15 JP6.16
P77: JP6.17 JP6.18 R8.1 U3.10 | length 1622.7
  Top Layer w8: v2(1408.11,1498.11) U3.10 1408.11,1580 ; JP6.18 2360,1710 2456.99,1710 R8.1 ; R8.1@2612.54,1855.55 2622.54,1855.55 R8.1@2632.54,1865.55
  Bottom Layer w8: v2(1408.11,1498.11) 2048.11,1498.11 JP6.17 JP6.18
RST: C10.2 J6.17 J6.18 J8.6 R3.2 SW1.2 U3.7 | length 3321.2
  Top Layer w8: C10.2 620,125.4 655.4,90 767,90 R3.2@801.34,124.34 ; R3.2@801.34,119.34 R3.2@801.34,124.34 ; R3.2 R3.2@801.34,130 ; v2(1310,1810) 1310,1770 1349.06,1730.94 U3.7 1349.06,1589.06 1210,1450 1210,1250 1140,1180 1140,690 J6.18 J6.17 890,110 821.34,110 R3.2@801.34,130 ; R3.2@801.34,124.34 R3.2@801.34,130
  Bottom Layer w8: J8.6@400,2190 820,2190 990,2020 1085,2020 1292.5,1812.5 1310,1812.5 1312.5,1812.5 v2@1315,1810
USB_BUSY: JP3.2 R2.1 U1.24 | length 793.2
  Top Layer w8: v2(1821.84,640) 1822.84,639 2060,639 2076.96,622.04 2076.96,576.52 2076.96,574.66 2078.82,572.8 2078.82,486.18 ; R2.1@2170,395 2078.82,486.18 ; R2.1@2173,392 2078.82,486.18
  Bottom Layer w8: 1690,640 v2(1821.84,640)
USB_OK: R1.1 U1.26 | length 295.8
  Top Layer w8: U1.26@2130,560 2130,475 2155,450 2217.32,450 R1.1@2297.32,370
VDD: C9.1 C10.1 D3.1 D4.1 D5.1 D6.1 J2.1 J2.2 J2.3 J5.1 J5.2 J7.1 J8.3 JP4.1 JP4.2 JP5.1 JP5.2 JP6.1 JP6.2 R4.1 R5.1 R9.2 R10.2 SW1.1 SW2.2 U3.55 U3.56 | length 10464.6
  Top Layer w11: C9.1 1085.08,1875.08 1106.22,1896.22 U3.56 ; C9.1@1071.18,1890 1097.08,1915.91 U3.55
  Top Layer w20: J8.3 470,1980 470,2310 550,2390 1880,2390 ; v6(1000,1540) 1000,1780 1056.26,1836.26 C9.1 ; R4.1 2240,1280 2370,1410 2370,1586.61 2423.39,1640 2690,1640
  Top Layer w30: 30,759.91 30,290 60,260 180,260 300,140 C10.1 537.32,72.68 570,40 1105.59,40 SW1.1@1165.59,100 ; 30,760 71.83,801.83 R10.2@74.33,804.33 ; R10.2@74.33,799.33 R10.2@75,800 ; R10.2@75.09,805 75.09,925 75.09,1040 J5.2@75.09,1140 ; J5.2 310,1360 J7.1 ; SW1.1@1169.43,96.16 D3.1 ; JP5.2 JP5.1 JP6.1 JP6.2 2370,2440 2420,2390 2420,2159.39 D5.1 D6.1 2668.7,2159.39 2690,2138.1 2690,1640 SW2.2 2790,1540 J2.3 J2.2 J2.1 ; R5.1 R4.1
  Bottom Layer w20: J7.1@380,1360 335,1360 320,1375 320,1830 J8.3 J8.3@400,1890 ; J7.1 400,1360 580,1540 JP4.2 JP4.1 v6(1000,1540)
VDD3: C8.1 J4.3 U2.1 | length 256.8
  Top Layer w30: J4.3@2460,1202 J4.3 2460,1300 2480,1320 C8.1@2538.66,1320 ; U2.1@2541.89,1248.11 C8.1@2541.89,1320
VDD5: C2.2 C5.1 C7.1 D1.2 D2.1 J4.1 U1.27 U2.3 | length 1759.4
  Top Layer w13: U1.27@2155.59,569 2155.59,484.41 2165,475 2240,475 ; 2175,475 2240,475 ; C2.2@2290,475 2280,475 2240,475
  Top Layer w30: C2.2@2290,475 2311.94,453.06 v2(2392,453.06) 2392,142 2346.16,96.16 D2.1 ; v7(2448.66,988) C7.1@2448.66,1018.66
  Top Layer w40: 2460,1100 C7.1 C5.1 ; J4.1@2460,1120.94 U2.3 ; 2560,900 C5.1@2560,1000.94
  Bottom Layer w30: v2@2390,453.06 2390,870 2448.66,928.66 v7(2448.66,988)
pads on no net: J1.0 J5.19 J5.20 J5.23 J5.24 JP4.17 JP4.18 U1.6 U1.9 U1.10 U1.11 U1.12 U1.13 U1.14 U1.15 U1.16 U1.17 U1.18 U1.19 U1.20 U1.21 U1.22 U1.25 U3.1 U3.48

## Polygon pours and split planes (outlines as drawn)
GND_POWER on Top Layer "Bottom Layer-No Net" (hatched 90Degree grid 10 track 10, remove dead copper, pour order 1001): 20.05,21.02 2820.05,21.02 2820.05,2492.02 20.05,2492.02
GND_POWER on Bottom Layer "Bottom Layer-No Net" (hatched 90Degree grid 10 track 10, remove dead copper, pour order 1001): 20,24 2820,24 2820,2495 20,2495

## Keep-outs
Keep-Out Layer:
  circle w10: c2730,2390 r120
  circle w5: c120,120 r110
  circle w10: c120,2390 r120
  circle w10: c2730,120 r120

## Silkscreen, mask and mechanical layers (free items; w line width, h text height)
Top Overlay:
  text "VDD" at 2038.99,2421.31 h35
  text "GND" at 750,2420 h35
  text "P70" at 2038.99,2321.31 h35
  text "P71" at 2038.99,2221.31 h35
  text "P46" at 750,2220 h35
  text "GND" at 1010,2190 h35 r90
  text "P57" at 1110,2190 h35 r90
  text "P56" at 1210,2190 h35 r90
  text "P55" at 1310,2190 h35 r90
  text "P54" at 1410,2190 h35 r90
  text "P53" at 1510,2190 h35 r90
  text "P52" at 1610,2190 h35 r90
  text "P51" at 1710,2190 h35 r90
  text "P50" at 1810,2190 h35 r90
  text "VDD" at 1910,2190 h35 r90
  text "RST" at 460,2180 h33 r90
  text "P01" at 752,2122 h35
  text "P72" at 2038.99,2121.31 h35
  text "GND" at 460,2070 h33 r90
  text "P73" at 2038.99,2021.31 h35
  text "P00" at 750,2020 h35
  text "SDA" at 460,1965 h33 r90
  text "P74" at 2038.99,1921.31 h35
  text "P43" at 750,1920 h35
  text "ICP" at 520,1910 h45 r90
  text "VDD" at 460,1865 h33 r90
  text "P75" at 2038.99,1821.31 h35
  text "P42" at 750,1820 h35
  text "GND" at 2710,1820 h50
  text "SCL" at 460,1765 h33 r90
  text "P76" at 2038.99,1721.31 h35
  text "P41" at 750,1720 h35
  text "POWER" at 2490,1710 h50
  text "On" at 2370,1670 h45
  text "Off" at 2740,1670 h45
  text "P30" at 460,1665 h33 r90
  text "P77" at 2038.99,1621.31 h35
  text "P40" at 750,1620 h35
  text "GND" at 460,1530 h33 r90
  text "GND" at 2038.99,1521.31 h35
  text "VDD" at 750,1520 h35
  text "P31" at 460,1430 h33 r90
  text "ISP" at 520,1410 h45 r90
  text "VDD" at 2710,1410 h50
  text "VDD" at 460,1320 h33 r90
  text "P07" at 910,1205 h38 r90
  text "P46" at 1110,1205 h38 r90
  text "P27" at 1310,1205 h38 r90
  text "P26" at 1410,1205 h38 r90
  text "P25" at 1510,1205 h38 r90
  text "P24" at 1610,1205 h38 r90
  text "P23" at 1710,1205 h38 r90
  text "P22" at 1810,1205 h38 r90
  text "P06" at 812,1204 h38 r90
  text "P44" at 210,1202 h40 r90
  text "P45" at 310,1202 h40 r90
  text "P02" at 411,1202 h38 r90
  text "P03" at 511,1202 h38 r90
  text "P04" at 611,1202 h38 r90
  text "P05" at 711,1202 h38 r90
  text "VDD" at 109,1201 h40 r90
  text "P21" at 1920,1200 h38 r90
  text "P20" at 2060,1200 h38 r90
  text "VDD3" at 2307.25,1197 h33
  text "VDD" at 2307.25,1147 h33
  text "VDD5" at 2307.25,1097 h33
  text "P31" at 1410,820 h35
  text "MA807" at 588.66,752 h50
  text "P30" at 1410,720 h35
  text "LQFP64(10x10)" at 585.66,679.34 h50
  text "P51" at 1410,620 h35
  text "Ev Board" at 582.66,602.34 h50
  text "TH150B_V11" at 581.66,525.34 h50
  text "P10" at 30,235 h40
  text "P11" at 150,230 h40
  text "P31" at 1115,191.5 h35 r90
  text "P12" at 305,190 h40 r90
  text "P13" at 415,190 h40 r90
  text "P14" at 510,190 h40 r90
  text "P15" at 605,190 h40 r90
  text "P16" at 710,190 h40 r90
  text "P17" at 810,190 h40 r90
  text "P30" at 1017.42,189.08 h35 r90
  text "RST" at 910,185 h40 r90
  text "P33" at 1310,185 h40 r90
  text "P34" at 1415,185 h40 r90
  text "P32" at 1212,175 h40 r90
  text "P35" at 1512,175 h40 r90
  text "P36" at 1612,175 h40 r90
  text "P37" at 1710,175 h40 r90
  text "P60" at 1810,175 h40 r90
  text "P61" at 1910,175 h40 r90
  text "GND" at 2010,175 h40 r90
  text "Reset" at 1220,80 h40
  text "USB_Busy" at 1840,60 h37
  text "USB_Ok" at 2380,50 h37
Mechanical 1:
  lines w13: 0,0 0,2510 2850,2510 2850,0 0,0

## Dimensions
0,2510 to 0,0 on Top Overlay
0,0 to 2850,0 on Top Overlay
